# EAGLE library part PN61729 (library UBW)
BERG USB connector
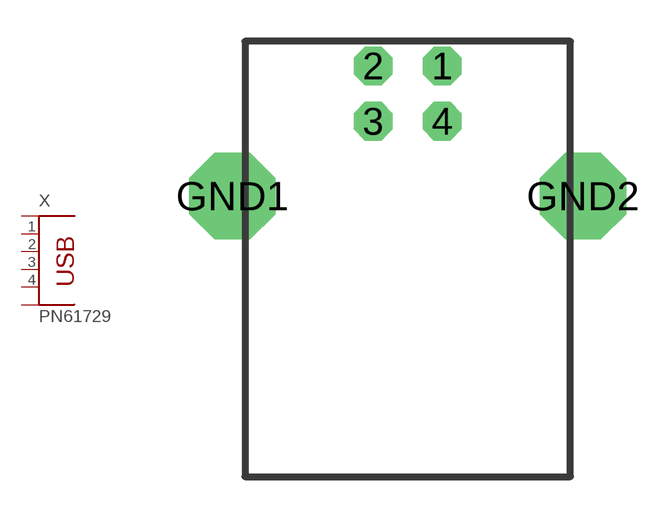
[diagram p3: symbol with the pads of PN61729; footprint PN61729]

Designator prefix X

## PN61729  [PN61729]
1  1
2  2
3  3
4  4
GND1  G1  pwr
GND2  G2  pwr

## Footprint PN61729 (pad centres in mm)
BERG
drill 0.9 octagon: 1 1.25,4.71; 2 -1.25,4.71; 3 -1.25,2.71; 4 1.25,2.71
drill 2.108 octagon: GND1 -6.35,0; GND2 6.35,0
